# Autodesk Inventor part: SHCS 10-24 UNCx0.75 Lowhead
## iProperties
Title: SHCS 10-24 UNCx0.75 Lowhead
Author: Neil Munro
Shininess: 48.0
PropertySet Name: _Private Model Information
Created: 2001-02
Part Number: SHCS 10-24 UNCx0.75 Lowhead
Material: Steel, Mild
Document SubType Name: Modeling
Designer: Administrator
Control State: 0
Master: False
Checked Out: False
PropertySet Name: Design Tracking Control
Density: 7.86
Volumn: 0.4698874259452923
Area: 5.082331744338173
PropertySet Name: Model Information
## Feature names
1. Body [Extrusion]
2. Head [Extrusion]
3. Hex [Extrusion]
4. Chamfer1
